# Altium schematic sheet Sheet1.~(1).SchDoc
size A; SheetNumber: 1; SheetTotal: 1
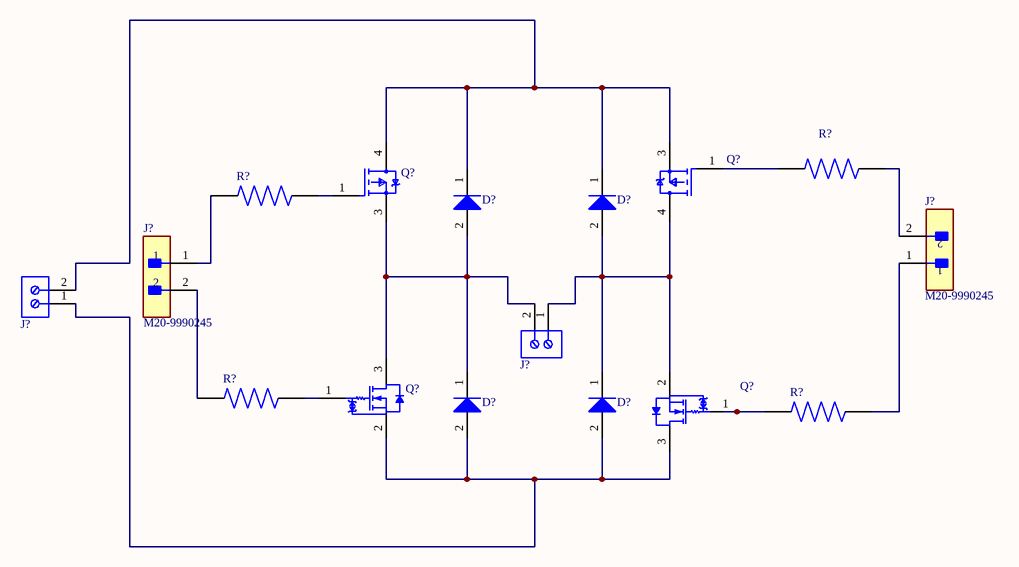
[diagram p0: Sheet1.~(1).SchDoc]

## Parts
(Parts that share a designator on the sheet are numbered #1, #2 ... from top to bottom, then left to right.)
D?#1  BAT54HT1G  [ONSC-SOD-323-2-477-02_V]  (value not drawn)
D?#2  BAT54HT1G  [ONSC-SOD-323-2-477-02_V]  (value not drawn)
D?#3  BAT54HT1G  [ONSC-SOD-323-2-477-02_V]  (value not drawn)
D?#4  BAT54HT1G  [ONSC-SOD-323-2-477-02_V]  (value not drawn)
J?#1  M20-9990245  [FP-M20-9990245-MFG]
J?#2  M20-9990245  [FP-M20-9990245-MFG]
J?#3  691214110002  [691214110002]  (value not drawn)
J?#4  691214110002  [691214110002]  (value not drawn)
Q?#1  NTB25P06T4G  [FP-418B-04-MFG]  (value not drawn)
Q?#2  NTB25P06T4G  [FP-418B-04-MFG]  (value not drawn)
Q?#3  2N7002WT1G  [ONSC-SC-70-3-419-04_V]  (value not drawn)
Q?#4  2N7002WT1G  [ONSC-SC-70-3-419-04_V]  (value not drawn)
R?#1  RNC55H3300BSRE6  [RESAD1081W64L635D269]  (value not drawn)
R?#2  RNC55H3300BSRE6  [RESAD1081W64L635D269]  (value not drawn)
R?#3  RNC55H3300BSRE6  [RESAD1081W64L635D269]  (value not drawn)
R?#4  RNC55H3300BSRE6  [RESAD1081W64L635D269]  (value not drawn)

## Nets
NetD?#1_1: D?#1.1(K) D?#2.1(K) J?#3.2 Q?#1.3(S) Q?#2.4(D)
NetD?#1_2: D?#1.2(A) D?#3.1(K) J?#4.2 Q?#2.3(S) Q?#3.3(D)
NetD?#2_2: D?#2.2(A) D?#4.1(K) J?#4.1 Q?#1.4(D) Q?#4.2(S)
NetD?#3_2: D?#3.2(A) D?#4.2(A) J?#3.1 Q?#3.2(S) Q?#4.3(D)
NetJ?#1_1: J?#1.1 R?#2.1
NetJ?#1_2: J?#1.2 R?#3.1
NetJ?#2_1: J?#2.1 R?#4.2
NetJ?#2_2: J?#2.2 R?#1.2
NetQ?#1_1: Q?#1.1(G) R?#1.1
NetQ?#2_1: Q?#2.1(G) R?#2.2
NetQ?#3_1: Q?#3.1(G) R?#3.2
NetQ?#4_1: Q?#4.1(G) R?#4.1

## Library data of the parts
D?#1-D?#4 = CMP-1055-00462-1: Schottky Barrier Diode, 2-Pin SOD-323, Pb-Free, Tape and Reel; Manufacturer: On Semiconductor; Configuration: Single; trr Max (ns): 5; IFSM Max (A): 0.6
J?#1 J?#2 = CMP-15831-000105-1: CONN HEADER VERT 2POS 2.54MM; Working Voltage: 750V; Gender: Male; Number of Poles: 2; Current Rating: 3A; Mated Stacking Heights: 16.54mm; Contact Resistance: 25mR; Connector Type: Male Pin; Insulation Resistance: 10GR; Mating Cycles: 300; Voltage: 50V
J?#3 J?#4 = CMP-1502-02464-2: NexarPartId: 18818288; Plating: Brass, Steel; Current: 10A; Pitch: 3.5052mm; Number of Levels: 1; Number of Contacts: 2; Wire Gauge (Min): 16AWG; Voltage: 300V; Wire Gauge (Max): 24AWG; Stripping Length: -6mm
Q?#1 Q?#2 = CMP-1058-00100-2: Manufacturer Lifecycle Status: ACTIVE; NexarPartId: 341266; Turn-On Delay Time: 14ns; Number of Elements: 1; Max Junction Temperature (Tj): 175°C; Power Dissipation: 120W; Voltage Rating (DC): -60V; Gate to Source Voltage (Vgs): 15V; Drain to Source Resistance: 65mΩ; Current Rating: -25A; Turn-Off Delay Time: 43ns; Continuous Drain Current (ID): 27.5A; Rds On Max: 82mΩ; Rise Time: 72ns; Fall Time: 190ns; Input Capacitance: 1.68nF; Element Configuration: Single
Q?#3 Q?#4 = CMP-1058-00618-1: Small Signal MOSFET, 60 V, 340 mA, Single, N-Channel, 3-Pin SC70, Pb-Free, Tape and Reel; Manufacturer: On Semiconductor; Crss Typ (pF): 2.2; Coss Typ (pF): 4.2; VGS(th) Max (V): 2.5; Channel Polarity: N Channel; ID Max (A): 0.34; VGS Max (V): 20; V(BR)DSS Min (V): 60; Ciss Typ (pF): 24.5
R?#1-R?#4 = RNC55H3300BSRE6: 330 Ohms Â±0.1% 0.125W, 1/8W Through Hole Resistor Axial Military, Moisture Resistant, Weldable Metal Film; MF: Vishay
